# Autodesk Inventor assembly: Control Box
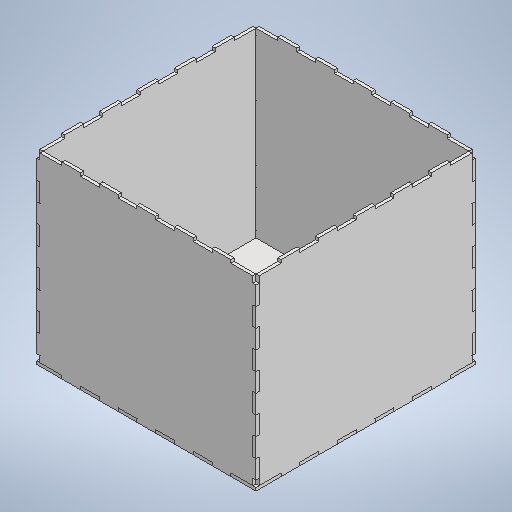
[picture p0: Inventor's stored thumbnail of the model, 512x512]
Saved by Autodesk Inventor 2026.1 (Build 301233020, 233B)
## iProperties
Created: 2026-11
Part Number: Control Box
Document SubType Name: Assembly
Designer: hp
Author: hp
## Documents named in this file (6)
- C:\Users\hp\Documents\Inventor\DOM1_CartesianRobot\Control Box.iam
- C:\Users\hp\Documents\Inventor\DOM1_CartesianRobot\Bottom of Control Box.ipt
- C:\Users\hp\Documents\Inventor\DOM1_CartesianRobot\Right of Control Box.ipt
- C:\Users\hp\Documents\Inventor\DOM1_CartesianRobot\Left of Control Box.ipt
- C:\Users\hp\Documents\Inventor\DOM1_CartesianRobot\Front of Control Box.ipt
- C:\Users\hp\Documents\Inventor\DOM1_CartesianRobot\Back of Control Box.ipt
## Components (5 placed, 5 different names)
1. Bottom of Control Box:1 — Mate:1, Flush:1, Mate:2, Mate:3, Flush:2, Mate:4, Mate:5, Flush:3, Mate:6, Flush:5
2. Right of Control Box:1 — Mate:3, Flush:2, Mate:4, Mate:7
3. Left of Control Box:1 — Mate:1, Flush:1, Mate:2, Flush:4
4. Front of Control Box:1 — Mate:5, Flush:3, Flush:4
5. Back of Control Box:1 — Mate:6, Flush:5, Mate:7
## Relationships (12: Mate 7, Flush 5)
- Mate:1: Bottom of Control Box:1 ↔ Left of Control Box:1
- Flush:1: Bottom of Control Box:1 ↔ Left of Control Box:1
- Mate:2: Bottom of Control Box:1 ↔ Left of Control Box:1
- Mate:3: Bottom of Control Box:1 ↔ Right of Control Box:1
- Flush:2: Bottom of Control Box:1 ↔ Right of Control Box:1
- Mate:4: Bottom of Control Box:1 ↔ Right of Control Box:1
- Mate:5: Bottom of Control Box:1 ↔ Front of Control Box:1
- Flush:3: Bottom of Control Box:1 ↔ Front of Control Box:1
- Flush:4: Left of Control Box:1 ↔ Front of Control Box:1
- Mate:6: Bottom of Control Box:1 ↔ Back of Control Box:1
- Flush:5: Bottom of Control Box:1 ↔ Back of Control Box:1
- Mate:7: Right of Control Box:1 ↔ Back of Control Box:1
